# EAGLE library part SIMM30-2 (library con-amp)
AMP connector
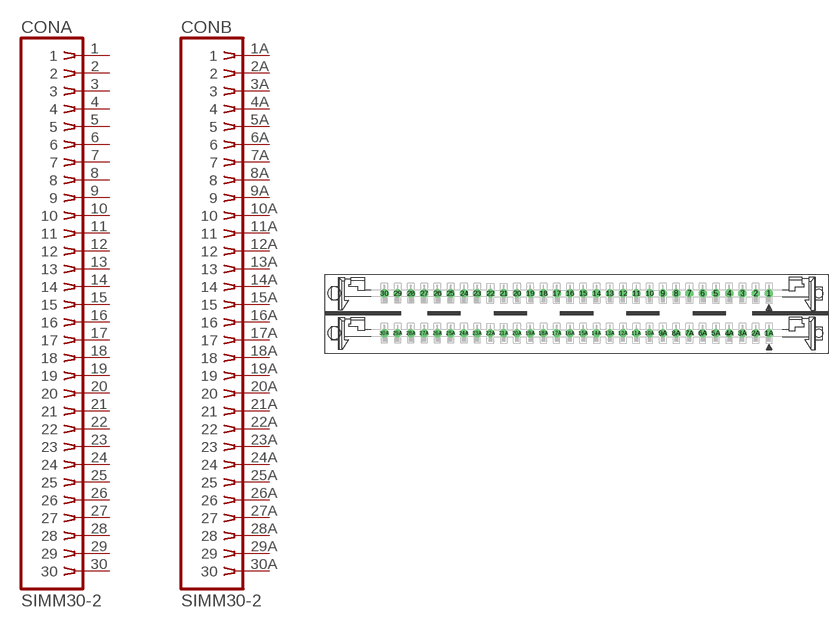
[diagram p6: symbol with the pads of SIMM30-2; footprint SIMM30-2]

Designator prefix CON; gates A=S30A B=S30A

## SIMM30-2 (OC_FARNELL: unknown; OC_NEWARK: unknown)  [SIMM30-2]
1  A:1  pas
1A  B:1  pas
2  A:2  pas
2A  B:2  pas
3  A:3  pas
3A  B:3  pas
4  A:4  pas
4A  B:4  pas
5  A:5  pas
5A  B:5  pas
6  A:6  pas
6A  B:6  pas
7  A:7  pas
7A  B:7  pas
8  A:8  pas
8A  B:8  pas
9  A:9  pas
9A  B:9  pas
10  A:10  pas
10A  B:10  pas
11  A:11  pas
11A  B:11  pas
12  A:12  pas
12A  B:12  pas
13  A:13  pas
13A  B:13  pas
14  A:14  pas
14A  B:14  pas
15  A:15  pas
15A  B:15  pas
16  A:16  pas
16A  B:16  pas
17  A:17  pas
17A  B:17  pas
18  A:18  pas
18A  B:18  pas
19  A:19  pas
19A  B:19  pas
20  A:20  pas
20A  B:20  pas
21  A:21  pas
21A  B:21  pas
22  A:22  pas
22A  B:22  pas
23  A:23  pas
23A  B:23  pas
24  A:24  pas
24A  B:24  pas
25  A:25  pas
25A  B:25  pas
26  A:26  pas
26A  B:26  pas
27  A:27  pas
27A  B:27  pas
28  A:28  pas
28A  B:28  pas
29  A:29  pas
29A  B:29  pas
30  A:30  pas
30A  B:30  pas

## Footprint SIMM30-2 (pad centres in mm)
SIMM connector
drill 1.016 octagon: 1 35.56,3.81; 1A 35.56,-3.81; 2 33.02,3.81; 2A 33.02,-3.81; 3 30.48,3.81; 3A 30.48,-3.81; 4 27.94,3.81; 4A 27.94,-3.81; 5 25.4,3.81; 5A 25.4,-3.81; 6 22.86,3.81; 6A 22.86,-3.81; 7 20.32,3.81; 7A 20.32,-3.81; 8 17.78,3.81; 8A 17.78,-3.81; 9 15.24,3.81; 9A 15.24,-3.81; 10 12.7,3.81; 10A 12.7,-3.81; 11 10.16,3.81; 11A 10.16,-3.81; 12 7.62,3.81; 12A 7.62,-3.81; 13 5.08,3.81; 13A 5.08,-3.81; 14 2.54,3.81; 14A 2.54,-3.81; 15 0,3.81; 15A 0,-3.81; 16 -2.54,3.81; 16A -2.54,-3.81; 17 -5.08,3.81; 17A -5.08,-3.81; 18 -7.62,3.81; 18A -7.62,-3.81; 19 -10.16,3.81; 19A -10.16,-3.81; 20 -12.7,3.81; 20A -12.7,-3.81; 21 -15.24,3.81; 21A -15.24,-3.81; 22 -17.78,3.81; 22A -17.78,-3.81; 23 -20.32,3.81; 23A -20.32,-3.81; 24 -22.86,3.81; 24A -22.86,-3.81; 25 -25.4,3.81; 25A -25.4,-3.81; 26 -27.94,3.81; 26A -27.94,-3.81; 27 -30.48,3.81; 27A -30.48,-3.81; 28 -33.02,3.81; 28A -33.02,-3.81; 29 -35.56,3.81; 29A -35.56,-3.81; 30 -38.1,3.81; 30A -38.1,-3.81
hole 2.413 at -47.65,3.835
hole 1.6 at 45.085,3.81
hole 2.413 at -47.65,-3.785
hole 1.6 at 45.085,-3.81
